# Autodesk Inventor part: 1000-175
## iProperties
Created: 2007-03
Part Number: 1000-175
Document SubType Name: Modeling
Designer: Andy Moles
Material: Steel
Author: Andy Moles
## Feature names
1. Base1
